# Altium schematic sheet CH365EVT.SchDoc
size A4; SheetNumber: 0; SheetTotal: 0
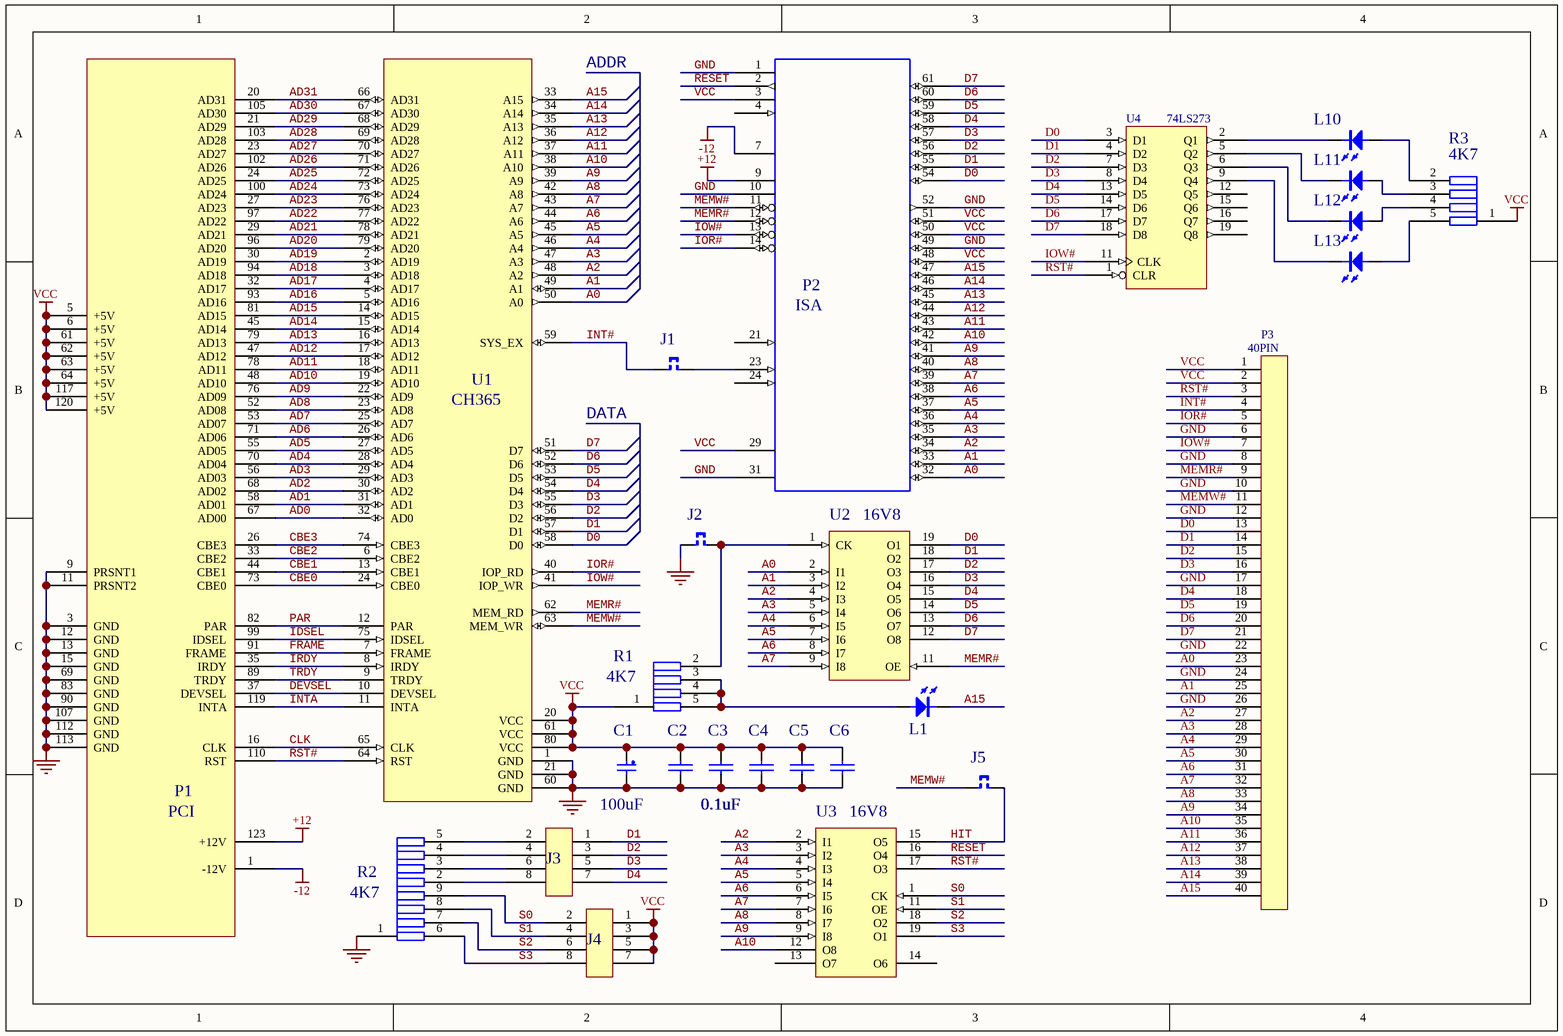
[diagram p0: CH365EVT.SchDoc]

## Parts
C1  100uF  [CD0.1]
C2  0.1uF  [RC1]
C3  0.1uF  [RC1]
C4  0.1uF  [RC1]
C5  0.1uF  [RC1]
C6  0.1uF  [RC1]
J1  (no value)  [SIP2]
J2  (no value)  [SIP2]
J3  4PIN  [IDC8]  (value not drawn)
J4  4PIN  [IDC8]  (value not drawn)
J5  (no value)  [SIP2]
L1  (no value)  [DIODE0.1]
L10  (no value)  [DIODE0.1]
L11  (no value)  [DIODE0.1]
L12  (no value)  [DIODE0.1]
L13  (no value)  [DIODE0.1]
P1  PCI  [PCI32]
P2  ISA  [PC_BUS]
P3  40PIN  [IDC40]
R1  4K7  [SIP5]
R2  4K7  [SIP9]
R3  4K7  [SIP5]
U1  CH365  [PQFP80]
U2  16V8  [DIP20]
U3  16V8  [DIP20]
U4  74LS273  [DIP20]

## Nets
+12: P1.123(+12V) P2.9(+12V)
-12: P1.1(-12V) P2.7(-12V)
GND: C1.2 C2.2 C3.2 C4.2 C5.2 C6.2 J2.1 P1.3(GND) P1.9(PRSNT1) P1.11(PRSNT2) P1.12(GND) P1.13(GND) P1.15(GND) P1.69(GND) P1.83(GND) P1.90(GND) P1.107(GND) P1.112(GND) P1.113(GND) P2.1(GND) P2.10(GND) P2.31(GND) P2.49(SA17) P2.52(AEN) P3.6 P3.8 P3.10 P3.12 P3.17 P3.22 P3.24 P3.26 R2.1 U1.1(GND) U1.21(GND) U1.60(GND) U2.10(GND) U3.10(GND) U4.10(GND)
VCC: C1.1 C2.1 C3.1 C4.1 C5.1 C6.1 J4.1 J4.3 J4.5 J4.7 P1.5(+5V) P1.6(+5V) P1.61(+5V) P1.62(+5V) P1.63(+5V) P1.64(+5V) P1.117(+5V) P1.120(+5V) P2.3(+5V) P2.29(+5V) P2.48(SA16) P2.50(SA18) P2.51(SA19) P3.1 P3.2 R1.1 R3.1 U1.20(VCC) U1.61(VCC) U1.80(VCC) U2.20(VCC) U3.20(VCC) U4.20(VCC)
A0: P2.32(SA0) P3.23 U1.50(A0) U2.2(I1)
A1: P2.33(SA1) P3.25 U1.49(A1) U2.3(I2)
A2: P2.34(SA2) P3.27 U1.48(A2) U2.4(I3) U3.2(I1)
A3: P2.35(SA3) P3.28 U1.47(A3) U2.5(I4) U3.3(I2)
A4: P2.36(SA4) P3.29 U1.46(A4) U2.6(I5) U3.4(I3)
A5: P2.37(SA5) P3.30 U1.45(A5) U2.7(I6) U3.5(I4)
A6: P2.38(SA6) P3.31 U1.44(A6) U2.8(I7) U3.6(I5)
A7: P2.39(SA7) P3.32 U1.43(A7) U2.9(I8) U3.7(I6)
A8: P2.40(SA8) P3.33 U1.42(A8) U3.8(I7)
A9: P2.41(SA9) P3.34 U1.39(A9) U3.9(I8)
A10: P2.42(SA10) P3.35 U1.38(A10) U3.12(O8)
A11: P2.43(SA11) P3.36 U1.37(A11)
A12: P2.44(SA12) P3.37 U1.36(A12)
A13: P2.45(SA13) P3.38 U1.35(A13)
A14: P2.46(SA14) P3.39 U1.34(A14)
A15: L1.K P2.47(SA15) P3.40 U1.33(A15)
AD0: P1.67(AD00) U1.32(AD0)
AD1: P1.58(AD01) U1.31(AD1)
AD2: P1.68(AD02) U1.30(AD2)
AD3: P1.56(AD03) U1.29(AD3)
AD4: P1.70(AD04) U1.28(AD4)
AD5: P1.55(AD05) U1.27(AD5)
AD6: P1.71(AD06) U1.26(AD6)
AD7: P1.53(AD07) U1.25(AD7)
AD8: P1.52(AD08) U1.23(AD8)
AD9: P1.76(AD09) U1.22(AD9)
AD10: P1.48(AD10) U1.19(AD10)
AD11: P1.78(AD11) U1.18(AD11)
AD12: P1.47(AD12) U1.17(AD12)
AD13: P1.79(AD13) U1.16(AD13)
AD14: P1.45(AD14) U1.15(AD14)
AD15: P1.81(AD15) U1.14(AD15)
AD16: P1.93(AD16) U1.5(AD16)
AD17: P1.32(AD17) U1.4(AD17)
AD18: P1.94(AD18) U1.3(AD18)
AD19: P1.30(AD19) U1.2(AD19)
AD20: P1.96(AD20) U1.79(AD20)
AD21: P1.29(AD21) U1.78(AD21)
AD22: P1.97(AD22) U1.77(AD22)
AD23: P1.27(AD23) U1.76(AD23)
AD24: P1.100(AD24) U1.73(AD24)
AD25: P1.24(AD25) U1.72(AD25)
AD26: P1.102(AD26) U1.71(AD26)
AD27: P1.23(AD27) U1.70(AD27)
AD28: P1.103(AD28) U1.69(AD28)
AD29: P1.21(AD29) U1.68(AD29)
AD30: P1.105(AD30) U1.67(AD30)
AD31: P1.20(AD31) U1.66(AD31)
CBE0: P1.73(CBE0) U1.24(CBE0)
CBE1: P1.44(CBE1) U1.13(CBE1)
CBE2: P1.33(CBE2) U1.6(CBE2)
CBE3: P1.26(CBE3) U1.74(CBE3)
CLK: P1.16(CLK) U1.65(CLK)
D0: P2.54(SD0) P3.13 U1.58(D0) U2.19(O1) U4.3(D1)
D1: J3.1 P2.55(SD1) P3.14 U1.57(D1) U2.18(O2) U4.4(D2)
D2: J3.3 P2.56(SD2) P3.15 U1.56(D2) U2.17(O3) U4.7(D3)
D3: J3.5 P2.57(SD3) P3.16 U1.55(D3) U2.16(O4) U4.8(D4)
D4: J3.7 P2.58(SD4) P3.18 U1.54(D4) U2.15(O5) U4.13(D5)
D5: P2.59(SD5) P3.19 U1.53(D5) U2.14(O6) U4.14(D6)
D6: P2.60(SD6) P3.20 U1.52(D6) U2.13(O7) U4.17(D7)
D7: P2.61(SD7) P3.21 U1.51(D7) U2.12(O8) U4.18(D8)
DEVSEL: P1.37(DEVSEL) U1.10(DEVSEL)
FRAME: P1.91(FRAME) U1.7(FRAME)
HIT: J5.2 U3.15(O5)
IDSEL: P1.99(IDSEL) U1.75(IDSEL)
INT#: J1.1 P3.4 U1.59(SYS_EX)
INTA: P1.119(INTA) U1.11(INTA)
IOR#: P2.14(-I/OR) P3.5 U1.40(IOP_RD)
IOW#: P2.13(-I/OW) P3.7 U1.41(IOP_WR) U4.11(CLK)
IRDY: P1.35(IRDY) U1.8(IRDY)
MEMR#: P2.12(-SMEMR) P3.9 U1.62(MEM_RD) U2.11(OE)
MEMW#: J5.1 P2.11(-SMEMW) P3.11 U1.63(MEM_WR)
PAR: P1.82(PAR) U1.12(PAR)
RESET: P2.2(RSTDRV) U3.16(O4)
RST#: P1.110(RST) P3.3 U1.64(RST) U3.17(O3) U4.1(CLR)
S0: J4.2 R2.9 U3.1(CK)
S1: J4.4 R2.8 U3.11(OE)
S2: J4.6 R2.7 U3.18(O2)
S3: J4.8 R2.6 U3.19(O1)
TRDY: P1.89(TRDY) U1.9(TRDY)
NetJ1_2: J1.2 P2.23(IRQ5)
NetJ2_2: J2.2 R1.2 U2.1(CK)
NetJ3_2: J3.2 R2.5
NetJ3_4: J3.4 R2.4
NetJ3_6: J3.6 R2.3
NetJ3_8: J3.8 R2.2
NetL1_A: L1.A R1.3 R1.4 R1.5
NetL10_A: L10.A R3.2
NetL10_K: L10.K U4.2(Q1)
NetL11_A: L11.A R3.3
NetL11_K: L11.K U4.5(Q2)
NetL12_A: L12.A R3.4
NetL12_K: L12.K U4.6(Q3)
NetL13_A: L13.A R3.5
NetL13_K: L13.K U4.9(Q4)

Not connected (* = marked no-connect by the designer): P2 4(IRQ9) 21(IRQ7) 24(IRQ4); U3 13(O7) 14(O6); U4 12(Q5) 15(Q6) 16(Q7) 19(Q8)

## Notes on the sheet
- ADDR
- DATA

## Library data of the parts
C1 = Pro70E3.TMP_100u_5
C2-C6 = Pro70E3.TMP_0.1u_4
J1 J5 = Pro70E3.TMP_UnNamed_6
J2 = Pro70E3.TMP_UnNamed_1
J3 J4 = Pro70E3.TMP_4PIN_7
L1 L10-L13 = Pro70E3.TMP_UnNamed_3
P1 = Pro70E3.TMP_PCI_9
P2 = Pro70E3.TMP_ISA_13
R1 R3 = Pro70E3.TMP_4K7_2
R2 = Pro70E3.TMP_4K7_11
U1 = Pro70E3.TMP_CH361_8
U2 = Pro70E3.TMP_16V8_12
U3 = Pro70E3.TMP_16V8_10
